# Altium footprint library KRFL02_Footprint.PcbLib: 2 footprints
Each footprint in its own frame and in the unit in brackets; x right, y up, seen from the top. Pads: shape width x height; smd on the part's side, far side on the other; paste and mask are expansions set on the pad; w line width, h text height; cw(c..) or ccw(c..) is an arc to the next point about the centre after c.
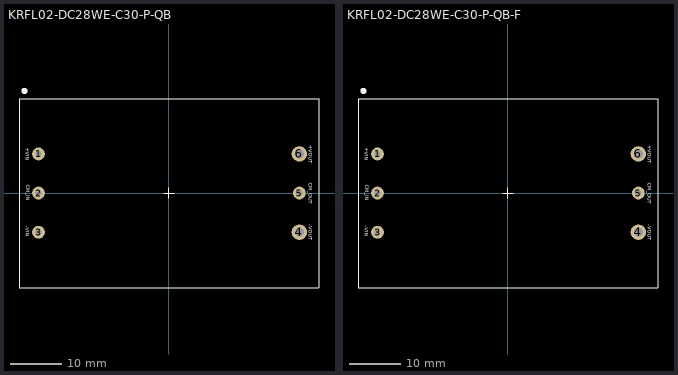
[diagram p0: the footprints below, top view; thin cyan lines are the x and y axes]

## KRFL02-DC28WE-C30-P-QB [mm] "KRFL02-DC28WE-C30-P-QB"
height 12.7
pads (6):
  round 2.5 hole 1.2: 1(-25.4,7.62) 2(-25.4,0) 3(-25.4,-7.62) 5(25.4,0)
  round 3 hole 1.75: 4(25.4,-7.62) 6(25.4,7.62)
Top Overlay:
  circle w1: c-28.15,19.905 r0.1
  lines w0.1: -1,0 0,0 ; 0,-1 0,0 ; 0,1 0,0 ; 1,0 0,0 ; -29.2,-18.419 29.222,-18.419 29.222,18.402 -29.2,18.402 -29.2,-18.419
  text "-VOUT" at 27.273,-6.025 h0.7
  text "CM_OUT" at 27.273,1.975 h0.7
  text "+VOUT" at 27.273,9.275 h0.7
  text "-VIN" at -27.917,-6.4 h0.7
  text "CM_IN" at -27.8,1.575 h0.7
  text "+VIN" at -27.917,8.845 h0.7
Bottom Overlay:
  circle w1: c-28.15,16.895 r0.1
  lines w0.1: -1,0 0,0 ; 0,-1 0,0 ; 0,1 0,0 ; 1,0 0,0 ; -29.2,-18.419 29.222,-18.419 29.222,18.402 -29.2,18.402 -29.2,-18.419
  text "-VOUT" at 27.273,-9.291 h0.7
  text "CM_OUT" at 27.273,-1.99 h0.7
  text "+VOUT" at 27.273,6.009 h0.7
  text "-VIN" at -27.917,-8.849 h0.7
  text "CM_IN" at -27.8,-1.574 h0.7
  text "+VIN" at -27.917,6.396 h0.7
3D body "KRFL02.STEP": height 12.71, standoff -4.29, extent -29.2,-18.419 29.222,18.4

## KRFL02-DC28WE-C30-P-QB-F [mm] "KRFL02-DC28WE-C30-P-QB-F"
height 12.7
pads (6):
  round 2.5 hole 1.2: 1(-25.4,7.62) 2(-25.4,0) 3(-25.4,-7.62) 5(25.4,0)
  round 3 hole 1.75: 4(25.4,-7.62) 6(25.4,7.62)
Top Overlay:
  circle w1: c-28.15,19.905 r0.1
  lines w0.1: -1,0 0,0 ; 0,-1 0,0 ; 0,1 0,0 ; 1,0 0,0 ; -29.2,-18.419 29.222,-18.419 29.222,18.402 -29.2,18.402 -29.2,-18.419
  text "-VOUT" at 27.273,-6.025 h0.7
  text "CM_OUT" at 27.273,1.975 h0.7
  text "+VOUT" at 27.273,9.275 h0.7
  text "-VIN" at -27.917,-6.4 h0.7
  text "CM_IN" at -27.8,1.575 h0.7
  text "+VIN" at -27.917,8.845 h0.7
Bottom Overlay:
  circle w1: c-28.15,16.895 r0.1
  lines w0.1: -1,0 0,0 ; 0,-1 0,0 ; 0,1 0,0 ; 1,0 0,0 ; -29.2,-18.419 29.222,-18.419 29.222,18.402 -29.2,18.402 -29.2,-18.419
  text "-VOUT" at 27.273,-9.291 h0.7
  text "CM_OUT" at 27.273,-1.99 h0.7
  text "+VOUT" at 27.273,6.009 h0.7
  text "-VIN" at -27.917,-8.849 h0.7
  text "CM_IN" at -27.8,-1.574 h0.7
  text "+VIN" at -27.917,6.396 h0.7
3D body "KRFL02_F.STEP": height 12.71, standoff -4.29, extent -29.2,-28 29.2,28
